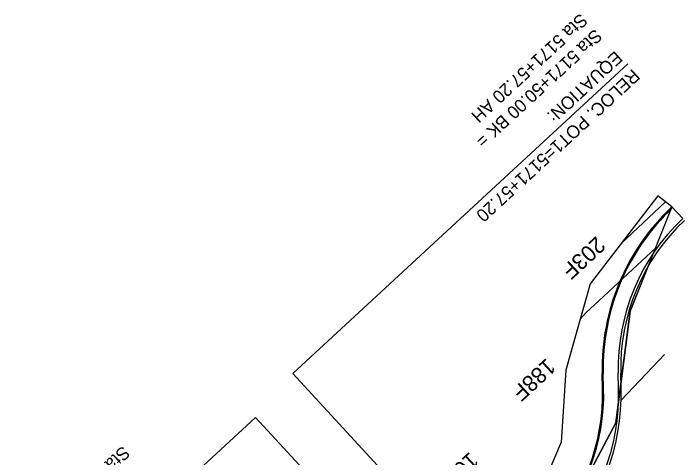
# Model space of a CAD drawing. Extents: x 2160876 to 2175990, y 601436 to 618246.
# Drawn here: x 2171733 to 2172362, y 613927 to 614343 of the extents above; entities that cross this region are included whole.
import ezdxf

# ---------------------------------------------------------------- set-up
doc = ezdxf.new("R2010")
doc.units = 0
for name, color, linetype in [('EX-UTIL-ELEC-TXT', 7, 'Continuous'), ('GN_Transparent 80', 7, 'Continuous'), ('RD_EX_DV_Prop_Property Lines', 7, 'Continuous'), ('RD_EX_Fence_Gate', 7, 'Continuous'), ('RD_EX_Parking_Conc', 7, 'Continuous'), ('RD_EX_RW', 7, 'Continuous'), ('RD_HC_TX_Sta50', 7, 'Continuous')]:
    doc.layers.add(name, color=color, linetype=linetype)

msp = doc.modelspace()

# ---------------------------------------------------------------- linework, layer by layer
at = {"layer": 'EX-UTIL-ELEC-TXT'}
for p, q in [((2172359.92, 614150.76), (2172349.66, 614161.69)), ((2172284.71, 613991.49), (2172284.36, 614005.61)), ((2172285.71, 613991.51), (2172285.36, 614005.63)), ((2172299.71, 613991.86), (2172299.36, 614005.98))]:
    msp.add_line(p, q, dxfattribs=at)
for centre, radius, start, end in [((2172491.3, 614010.74), 207, 133.1773, 181.42089), ((2172491.3, 614010.74), 206, 133.1773, 181.42089), ((2172491.3, 614010.74), 192, 133.1773, 181.42089), ((2172091.77, 613986.7), 193, 316.7496, 1.42089), ((2172091.77, 613986.7), 194, 317.04096, 1.42089), ((2172091.77, 613986.7), 208, 316.7496, 1.42089)]:
    msp.add_arc(centre, radius, start, end, dxfattribs=at)
at = {"layer": 'GN_Transparent 80'}
msp.add_line((2172302.04, 613991.92), (2172301.69, 614006.04), dxfattribs=at)
for centre, radius, start, end in [((2172491.3, 614010.74), 189.67, 133.1773, 181.42089), ((2172091.77, 613986.7), 210.33, 316.70481, 1.42089)]:
    msp.add_arc(centre, radius, start, end, dxfattribs=at)
at = {"layer": 'RD_EX_DV_Prop_Property Lines'}
msp.add_lwpolyline([(2172302.02, 613980.76), (2172342.61, 614023.56)], dxfattribs=at)
at = {"layer": 'RD_EX_Fence_Gate'}
msp.add_line((2172349.66, 614161.69), (2172336.34, 614172.04), dxfattribs=at)
msp.add_lwpolyline([(2172336.34, 614172.04), (2172273.18, 614089.51), (2172250.16, 614008.66), (2172245.97, 613941.37), (2172206.79, 613849.42)], dxfattribs=at)
at = {"layer": 'RD_EX_Parking_Conc'}
for p, q in [((2171994.38, 614005.75), (2172308.22, 614295.56)), ((2171959.47, 613964.42), (2171764.77, 613784.64))]:
    msp.add_line(p, q, dxfattribs=at)
msp.add_lwpolyline([(2172229.16, 613751.5), (2172189.72, 613715.07), (2171959.47, 613964.42)], dxfattribs=at)
at = {"layer": 'RD_EX_RW'}
for p, q in [((2172336.34, 614172.04), (2172302.22, 614127.45)), ((2172302.22, 614127.45), (2172343.51, 614166.47)), ((2172343.51, 614166.47), (2172336.34, 614172.04)), ((2172334.21, 614123.05), (2172304.05, 614094.89))]:
    msp.add_line(p, q, dxfattribs=at)
for points in [[(2172349.66, 614161.69), (2172310.65, 614064.12), (2172297.2, 613959.48), (2172234.36, 613840.69)], [(2172234.36, 613840.69), (2172297.2, 613959.48), (2172310.65, 614064.12), (2172334.21, 614123.05)], [(2172304.05, 614094.89), (2172281.27, 614073.62), (2172269.55, 614062.93), (2172263.79, 614056.53)], [(2172263.79, 614056.53), (2172250.16, 614008.66), (2172245.97, 613941.37), (2172206.79, 613849.42)]]:
    msp.add_lwpolyline(points, dxfattribs=at)
at = {"layer": 'RD_HC_TX_Sta50'}
msp.add_line((2172207.32, 613775.14), (2171994.38, 614005.75), dxfattribs=at)

# ---------------------------------------------------------------- texts
at = {"layer": 'RD_EX_Fence_Gate'}
for s, p in [('203F', (2172278.71, 614134.81)), ('188F', (2172232.19, 614020.78)), ('103F', (2172160.23, 613932.89))]:
    msp.add_text(s, height=15, rotation=222.71947, dxfattribs=at).set_placement(p)
at = {"layer": 'RD_EX_Parking_Conc'}
msp.add_text('Sta 5171+57.20 AH', height=12, rotation=222.71947, dxfattribs=at).set_placement((2171835.01, 613938.5))
at = {"layer": 'RD_HC_TX_Sta50'}
for s, p in [('Sta 5171+57.20 AH', (2172263.83, 614343.64)), ('Sta 5171+50.00 BK = ', (2172277.39, 614328.95)), ('EQUATION:', (2172296.39, 614308.37)), ('RELOC. POT1=5171+57.20', (2172312.73, 614291.51))]:
    msp.add_text(s, height=12, rotation=222.71947, dxfattribs=at).set_placement(p)

doc.saveas('drawing.dxf')
